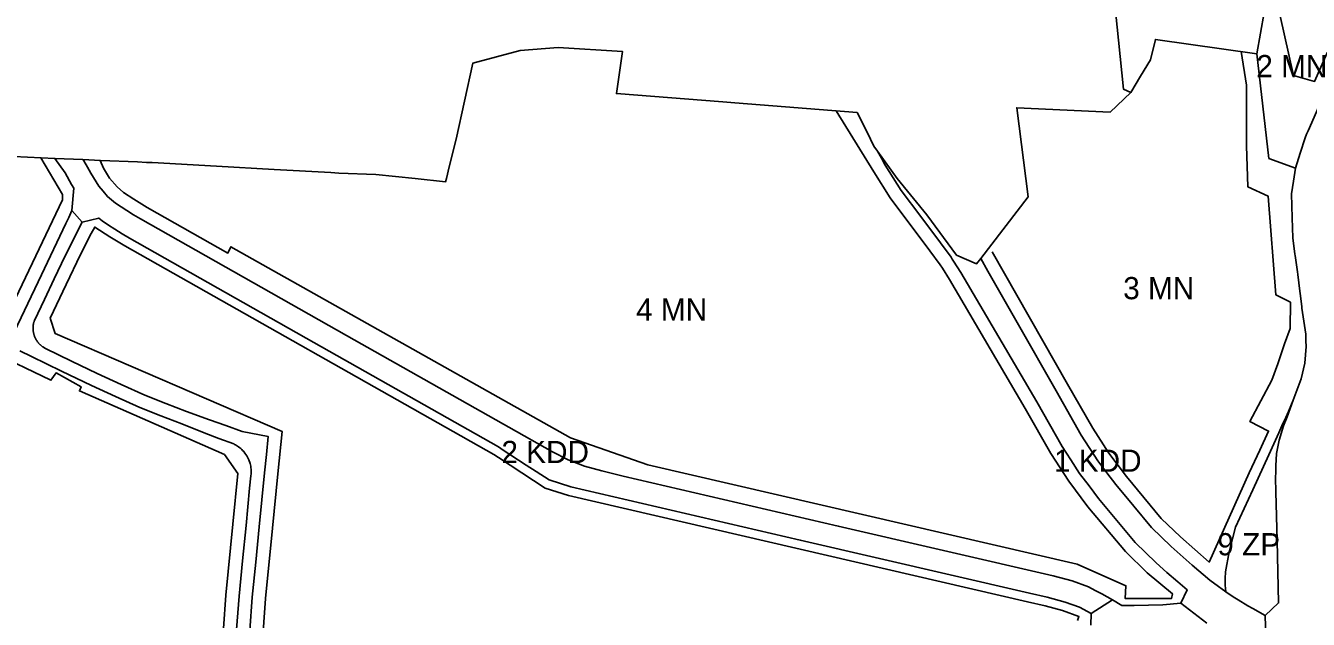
# Model space of a CAD drawing. Extents: x -294445 to -292055, y 21869 to 23693.
# Drawn here: x -294152 to -293575, y 22801 to 23069 of the extents above; entities that cross this region are included whole.
import ezdxf

# ---------------------------------------------------------------- set-up
doc = ezdxf.new("R2010")
doc.units = 0
for name, color, linetype in [('linie_rozgraniczajace', 7, 'Continuous'), ('linie_zabudowy_nieprzekraczalne', 7, 'Continuous'), ('oznaczenia_przeznaczen', 7, 'Continuous')]:
    doc.layers.add(name, color=color, linetype=linetype)

msp = doc.modelspace()

# ---------------------------------------------------------------- linework, layer by layer
at = {"layer": 'linie_rozgraniczajace'}
for points in [[(-293594.8, 23074.713), (-293598.18, 23056.18), (-293643.75, 23062.64), (-293646, 23053.44), (-293650.405, 23046.1), (-293654.81, 23038.76), (-293658.12, 23040.27), (-293663.22, 23090.34)], [(-293594.377, 22803.197), (-293588.38, 22808.908), (-293589.023, 22837.046), (-293589.523, 22858.895), (-293589.667, 22865.184), (-293589.623, 22867.888), (-293589.579, 22870.592), (-293589.304, 22876.246), (-293588.134, 22882.181), (-293586.073, 22888.643), (-293584.533, 22892.65), (-293583.08, 22896.428), (-293581.725, 22900.141), (-293578.212, 22909.773), (-293576.551, 22916.911), (-293575.931, 22924.43), (-293576.07, 22926.857), (-293576.139, 22929.92), (-293576.989, 22935.764), (-293577.839, 22941.607), (-293577.905, 22942.172), (-293578.488, 22947.138), (-293578.733, 22949.23), (-293579.627, 22956.854), (-293579.807, 22958.058), (-293580.261, 22961.104), (-293580.894, 22965.354), (-293580.971, 22965.973), (-293581.874, 22973.281), (-293582.075, 22977.797), (-293582.277, 22982.314), (-293582.433, 22987.716), (-293582.589, 22993.118), (-293581.675, 22998.875), (-293580.762, 23004.631), (-293578.598, 23011.442), (-293576.434, 23018.253), (-293575.727, 23019.979), (-293575.068, 23021.454), (-293563.422, 23048.255)], [(-294157.15, 23009.86), (-294138.732, 23009.066), (-294134.158, 23002.573), (-294131.211, 22997.34), (-294130.175, 22995.659), (-294131.07, 22985.54), (-294132.507, 22982.523), (-294133.797, 22979.815), (-294144.84, 22956.635), (-294158.61, 22927.73)], [(-293620.646, 22799.786), (-293632.243, 22808.79), (-293629.415, 22814.768), (-293633.738, 22818.381), (-293638.573, 22822.65), (-293643.408, 22826.92), (-293652.85, 22836.1), (-293661.114, 22846.024), (-293669.378, 22855.947), (-293673.604, 22861.583), (-293677.829, 22867.218), (-293681.733, 22873.257), (-293685.637, 22879.297), (-293691.388, 22889.378), (-293697.14, 22899.46), (-293714.205, 22928.55), (-293731.269, 22957.64), (-293732.897, 22960.234), (-293734.524, 22962.828), (-293735.093, 22963.688), (-293735.661, 22964.547), (-293740.366, 22971.031), (-293749.217, 22982.841), (-293758.069, 22994.65), (-293761.675, 23000.352), (-293765.28, 23006.054), (-293767.02, 23009.191), (-293768.761, 23012.328), (-293759.96, 23000), (-293746.54, 22983.64), (-293733.17, 22965.49), (-293724.23, 22961.52), (-293722.338, 22963.974), (-293719.124, 22958.324), (-293705.395, 22934.192), (-293688.451, 22904.41), (-293677.088, 22884.493), (-293669.62, 22872.939), (-293665.575, 22867.545), (-293661.531, 22862.15), (-293653.516, 22852.527), (-293645.502, 22842.903), (-293636.61, 22834.257), (-293627.186, 22825.936), (-293619.232, 22819.159), (-293615.314, 22816.339), (-293612.018, 22813.966), (-293608.745, 22811.61), (-293606.559, 22810.288), (-293602.186, 22807.646), (-293600, 22806.324), (-293594.377, 22803.197), (-293593.872, 22788.256)], [(-294158.61, 22927.73), (-294144.84, 22956.635), (-294133.797, 22979.815), (-294132.507, 22982.523), (-294131.07, 22985.54), (-294126.459, 22980.419), (-294132.54, 22968.508), (-294135.795, 22961.674), (-294139.05, 22954.84), (-294143.499, 22945.471), (-294147.949, 22936.102), (-294148.017, 22935.913), (-294148.081, 22935.721), (-294148.141, 22935.529), (-294148.198, 22935.336), (-294148.25, 22935.141), (-294148.299, 22934.945), (-294148.344, 22934.749), (-294148.385, 22934.551), (-294148.422, 22934.353), (-294148.455, 22934.154), (-294148.484, 22933.955), (-294148.509, 22933.755), (-294148.531, 22933.554), (-294148.548, 22933.353), (-294148.561, 22933.152), (-294148.57, 22932.951), (-294148.575, 22932.749), (-294148.577, 22932.548), (-294148.574, 22932.346), (-294148.567, 22932.145), (-294148.556, 22931.943), (-294148.542, 22931.742), (-294148.523, 22931.542), (-294148.5, 22931.341), (-294148.474, 22931.141), (-294148.443, 22930.942), (-294148.408, 22930.744), (-294148.37, 22930.546), (-294148.327, 22930.349), (-294148.281, 22930.152), (-294148.231, 22929.957), (-294148.177, 22929.763), (-294148.119, 22929.57), (-294148.057, 22929.378), (-294147.991, 22929.187), (-294147.922, 22928.998), (-294147.849, 22928.81), (-294147.772, 22928.624), (-294147.692, 22928.439), (-294147.608, 22928.256), (-294147.52, 22928.074), (-294147.429, 22927.894), (-294147.334, 22927.717), (-294147.235, 22927.541), (-294147.134, 22927.367), (-294147.028, 22927.195), (-294146.92, 22927.025), (-294146.808, 22926.857), (-294146.692, 22926.692), (-294146.574, 22926.529), (-294146.452, 22926.368), (-294146.327, 22926.21), (-294146.199, 22926.054), (-294146.068, 22925.901), (-294145.934, 22925.751), (-294145.797, 22925.603), (-294145.657, 22925.458), (-294145.514, 22925.316), (-294145.368, 22925.176), (-294145.22, 22925.04), (-294145.069, 22924.906), (-294144.915, 22924.776), (-294144.759, 22924.648), (-294144.6, 22924.524), (-294144.439, 22924.403), (-294144.275, 22924.285), (-294144.109, 22924.17), (-294143.941, 22924.059), (-294143.771, 22923.951), (-294143.707, 22923.912), (-294142.966, 22923.5), (-294131.334, 22917.829), (-294119.701, 22912.158), (-294108.982, 22907.305), (-294098.264, 22902.451), (-294088.881, 22898.77), (-294079.498, 22895.088), (-294069.14, 22891.36), (-294061.81, 22888.76), (-294054.48, 22886.16), (-294042.85, 22883.89), (-294043.645, 22875.72), (-294044.44, 22867.55), (-294045.63, 22855.355), (-294046.82, 22843.16), (-294048.39, 22827.29), (-294049.96, 22811.42), (-294051.011, 22796.447)], [(-294148.577, 22932.548), (-294148.575, 22932.749), (-294148.57, 22932.951), (-294148.561, 22933.152), (-294148.548, 22933.353), (-294148.531, 22933.554), (-294148.509, 22933.755), (-294148.484, 22933.955), (-294148.455, 22934.154), (-294148.422, 22934.353), (-294148.385, 22934.551), (-294148.344, 22934.749), (-294148.299, 22934.945), (-294148.25, 22935.141), (-294148.198, 22935.336), (-294148.141, 22935.529), (-294148.081, 22935.721), (-294148.017, 22935.913), (-294147.949, 22936.102), (-294143.499, 22945.471), (-294139.05, 22954.84), (-294135.795, 22961.674), (-294132.54, 22968.508), (-294126.459, 22980.419), (-294119.036, 22982.215), (-294117.521, 22980.923), (-294114.684, 22979.04), (-294111.847, 22977.158), (-294108.536, 22975.119), (-294105.226, 22973.08), (-294022.231, 22926.097), (-293939.236, 22879.115), (-293937.08, 22877.73), (-293926.755, 22870.99), (-293922.326, 22868.099), (-293916.467, 22864.266), (-293906.702, 22861.129), (-293803.525, 22837.225), (-293700.349, 22813.32), (-293692.398, 22811.487), (-293684.302, 22809.265), (-293677.89, 22806.933), (-293672.605, 22804.206), (-293672.799, 22798.844)], [(-294147.692, 22928.439), (-294147.772, 22928.624), (-294147.849, 22928.81), (-294147.922, 22928.998), (-294147.991, 22929.187), (-294148.057, 22929.378), (-294148.119, 22929.57), (-294148.177, 22929.763), (-294148.231, 22929.957), (-294148.281, 22930.152), (-294148.327, 22930.349), (-294148.37, 22930.546), (-294148.408, 22930.744), (-294148.443, 22930.942), (-294148.474, 22931.141), (-294148.5, 22931.341), (-294148.523, 22931.542), (-294148.542, 22931.742), (-294148.556, 22931.943), (-294148.567, 22932.145), (-294148.574, 22932.346), (-294148.577, 22932.548)], [(-294051.011, 22796.447), (-294049.96, 22811.42), (-294048.39, 22827.29), (-294046.82, 22843.16), (-294045.63, 22855.355), (-294044.44, 22867.55), (-294043.645, 22875.72), (-294042.85, 22883.89), (-294054.48, 22886.16), (-294061.81, 22888.76), (-294069.14, 22891.36), (-294079.498, 22895.088), (-294088.881, 22898.77), (-294098.264, 22902.451), (-294108.982, 22907.305), (-294119.701, 22912.158), (-294131.334, 22917.829), (-294142.966, 22923.5), (-294143.707, 22923.912), (-294143.771, 22923.951), (-294143.941, 22924.059), (-294144.109, 22924.17), (-294144.275, 22924.285), (-294144.439, 22924.403), (-294144.6, 22924.524), (-294144.759, 22924.648), (-294144.915, 22924.776), (-294145.069, 22924.906), (-294145.22, 22925.04), (-294145.368, 22925.176), (-294145.514, 22925.316), (-294145.657, 22925.458), (-294145.797, 22925.603), (-294145.934, 22925.751), (-294146.068, 22925.901), (-294146.199, 22926.054), (-294146.327, 22926.21), (-294146.452, 22926.368), (-294146.574, 22926.529), (-294146.692, 22926.692), (-294146.808, 22926.857), (-294146.92, 22927.025), (-294147.028, 22927.195), (-294147.134, 22927.367), (-294147.235, 22927.541), (-294147.334, 22927.717), (-294147.429, 22927.894), (-294147.52, 22928.074), (-294147.608, 22928.256), (-294147.692, 22928.439)], [(-294154.577, 22922.459), (-294149.34, 22919.92), (-294135.796, 22913.324), (-294122.252, 22906.727), (-294111.426, 22901.825), (-294100.599, 22896.922), (-294091.105, 22893.197), (-294081.611, 22889.472), (-294071.61, 22885.5), (-294064.97, 22882.989), (-294058.329, 22880.478), (-294057.979, 22880.268), (-294057.573, 22880.055), (-294057.092, 22879.779), (-294056.587, 22879.46), (-294056.171, 22879.174), (-294055.636, 22878.77), (-294055.183, 22878.394), (-294054.734, 22877.988), (-294054.307, 22877.565), (-294053.814, 22877.028), (-294053.288, 22876.384), (-294052.815, 22875.728), (-294052.434, 22875.134), (-294052.074, 22874.502), (-294051.756, 22873.867), (-294051.522, 22873.341), (-294051.313, 22872.812), (-294051.091, 22872.165), (-294050.935, 22871.631), (-294050.806, 22871.117), (-294050.678, 22870.493), (-294050.565, 22869.754), (-294050.497, 22869.087), (-294050.463, 22868.416), (-294050.459, 22867.875), (-294050.492, 22867.084), (-294050.603, 22866.172), (-294051.151, 22860.56), (-294051.971, 22852.154), (-294052.791, 22843.747), (-294054.365, 22827.836), (-294055.939, 22811.926), (-294056.993, 22796.91)], [(-294056.993, 22796.91), (-294055.939, 22811.926), (-294054.365, 22827.836), (-294052.791, 22843.747), (-294051.971, 22852.154), (-294051.151, 22860.56), (-294050.603, 22866.172), (-294050.492, 22867.084), (-294050.459, 22867.875), (-294050.463, 22868.416), (-294050.497, 22869.087), (-294050.565, 22869.754), (-294050.678, 22870.493), (-294050.806, 22871.117), (-294050.935, 22871.631), (-294051.091, 22872.165), (-294051.313, 22872.812), (-294051.522, 22873.341), (-294051.756, 22873.867), (-294052.074, 22874.502), (-294052.434, 22875.134), (-294052.815, 22875.728), (-294053.288, 22876.384), (-294053.814, 22877.028), (-294054.307, 22877.565), (-294054.734, 22877.988), (-294055.183, 22878.394), (-294055.636, 22878.77), (-294056.171, 22879.174), (-294056.587, 22879.46), (-294057.092, 22879.779), (-294057.573, 22880.055), (-294057.979, 22880.268), (-294058.329, 22880.478), (-294064.97, 22882.989), (-294071.61, 22885.5), (-294081.611, 22889.472), (-294091.105, 22893.197), (-294100.599, 22896.922), (-294111.426, 22901.825), (-294122.252, 22906.727), (-294135.796, 22913.324), (-294149.34, 22919.92), (-294154.577, 22922.459)], [(-293672.799, 22798.844), (-293672.605, 22804.206), (-293663.097, 22810.278), (-293658.78, 22807.8), (-293653.38, 22807.76), (-293646.929, 22807.926), (-293640.477, 22808.092), (-293632.243, 22808.79), (-293620.646, 22799.786)], [(-293574.744, 22625.222), (-293577.87, 22637.216), (-293579.304, 22644.235), (-293580.738, 22651.254), (-293582.053, 22659.409), (-293583.368, 22667.564), (-293584.1, 22672.161), (-293584.572, 22676.205), (-293585.045, 22680.249), (-293585.422, 22688.433), (-293585.799, 22696.617), (-293585.885, 22701.145), (-293585.97, 22705.674), (-293585.87, 22715.192), (-293585.77, 22724.711), (-293586.07, 22735.224), (-293586.369, 22745.737), (-293586.761, 22756.424), (-293587.153, 22767.111), (-293587.332, 22772.613), (-293587.511, 22778.115), (-293593.872, 22788.256), (-293594.377, 22803.197)]]:
    msp.add_lwpolyline(points, dxfattribs=at)
for points in [[(-293598.18, 23056.18), (-293594.8, 23074.713), (-293589.79, 23085.71), (-293551.776, 23075.056), (-293563.422, 23048.255), (-293575.068, 23021.454), (-293575.727, 23019.979), (-293576.434, 23018.253), (-293578.598, 23011.442), (-293580.762, 23004.631), (-293592.68, 23009.07)], [(-293722.338, 22963.974), (-293700.97, 22991.69), (-293706.09, 23031.87), (-293664.07, 23029.95), (-293654.81, 23038.76), (-293650.405, 23046.1), (-293646, 23053.44), (-293643.75, 23062.64), (-293598.18, 23056.18), (-293592.68, 23009.07), (-293580.762, 23004.631), (-293581.675, 22998.875), (-293582.589, 22993.118), (-293582.433, 22987.716), (-293582.277, 22982.314), (-293582.075, 22977.797), (-293581.874, 22973.281), (-293580.971, 22965.973), (-293580.894, 22965.354), (-293580.261, 22961.104), (-293579.807, 22958.058), (-293579.627, 22956.854), (-293578.733, 22949.23), (-293578.488, 22947.138), (-293577.905, 22942.172), (-293577.839, 22941.607), (-293576.989, 22935.764), (-293576.139, 22929.92), (-293576.07, 22926.857), (-293575.931, 22924.43), (-293576.551, 22916.911), (-293578.212, 22909.773), (-293581.725, 22900.141), (-293583.946, 22895.109), (-293585.157, 22892.364), (-293586.392, 22889.63), (-293588.262, 22885.537), (-293592.792, 22875.624), (-293600, 22859.85), (-293603.84, 22851.42), (-293607.68, 22842.99), (-293610.65, 22831.88), (-293612.28, 22822.97), (-293612.31, 22819.94), (-293612.34, 22816.91), (-293612.018, 22813.966), (-293615.314, 22816.339), (-293619.232, 22819.159), (-293627.186, 22825.936), (-293636.61, 22834.257), (-293645.502, 22842.903), (-293653.516, 22852.527), (-293661.531, 22862.15), (-293665.575, 22867.545), (-293669.62, 22872.939), (-293677.088, 22884.493), (-293688.451, 22904.41), (-293705.395, 22934.192), (-293719.124, 22958.324)], [(-294126.117, 23008.522), (-294118.18, 23008.18), (-294101.6, 23007.47), (-294097.5, 23007.29), (-294095.02, 23007.27), (-294066.09, 23005.62), (-294040.06, 23004.12), (-294014.7, 23002.66), (-294011.01, 23002.45), (-293994.39, 23001.87), (-293976.73, 23000), (-293963.03, 22998.55), (-293962.67, 23000), (-293961.4, 23005.29), (-293958.22, 23017.7), (-293950.78, 23051.9), (-293929.5, 23057.67), (-293912.35, 23058.96), (-293883.49, 23057.26), (-293886.21, 23038.22), (-293838.36, 23034.57), (-293832.98, 23034.12), (-293777.93, 23029.8), (-293773.46, 23020.81), (-293770.34, 23014.54), (-293768.761, 23012.328), (-293767.02, 23009.191), (-293765.28, 23006.054), (-293761.675, 23000.352), (-293758.069, 22994.65), (-293749.217, 22982.841), (-293740.366, 22971.031), (-293735.661, 22964.547), (-293735.093, 22963.688), (-293734.524, 22962.828), (-293732.897, 22960.234), (-293731.269, 22957.64), (-293714.205, 22928.55), (-293697.14, 22899.46), (-293691.388, 22889.378), (-293685.637, 22879.297), (-293681.733, 22873.257), (-293677.829, 22867.218), (-293673.604, 22861.583), (-293669.378, 22855.947), (-293661.114, 22846.024), (-293652.85, 22836.1), (-293643.408, 22826.92), (-293638.573, 22822.65), (-293633.738, 22818.381), (-293629.415, 22814.768), (-293632.243, 22808.79), (-293640.477, 22808.092), (-293646.929, 22807.926), (-293653.38, 22807.76), (-293658.78, 22807.8), (-293663.097, 22810.278), (-293667.82, 22812.99), (-293670.846, 22814.551), (-293673.872, 22816.113), (-293681.265, 22818.801), (-293689.751, 22821.13), (-293786.416, 22843.526), (-293883.08, 22865.921), (-293887.877, 22867.124), (-293892.674, 22868.327), (-293896.617, 22869.418), (-293900.561, 22870.51), (-293907.871, 22873.269), (-293914.956, 22876.861), (-294007.627, 22929.322), (-294100.299, 22981.782), (-294103.377, 22983.682), (-294106.455, 22985.581), (-294108.973, 22987.252), (-294111.49, 22988.922), (-294115.067, 22991.973), (-294117.039, 22994.289), (-294119.011, 22996.605), (-294122.595, 23002.419), (-294123.323, 23003.712), (-294124.144, 23005.17), (-294125.693, 23007.92)], [(-294138.732, 23009.066), (-294126.117, 23008.522), (-294125.693, 23007.92), (-294124.144, 23005.17), (-294123.323, 23003.712), (-294122.595, 23002.419), (-294119.011, 22996.605), (-294117.039, 22994.289), (-294115.067, 22991.973), (-294111.49, 22988.922), (-294108.973, 22987.252), (-294106.455, 22985.581), (-294103.377, 22983.682), (-294100.299, 22981.782), (-294007.627, 22929.322), (-293914.956, 22876.861), (-293907.871, 22873.269), (-293900.561, 22870.51), (-293896.617, 22869.418), (-293892.674, 22868.327), (-293887.877, 22867.124), (-293883.08, 22865.921), (-293786.416, 22843.526), (-293689.751, 22821.13), (-293681.265, 22818.801), (-293673.872, 22816.113), (-293670.846, 22814.551), (-293667.82, 22812.99), (-293663.097, 22810.278), (-293672.605, 22804.206), (-293677.89, 22806.933), (-293684.302, 22809.265), (-293692.398, 22811.487), (-293700.349, 22813.32), (-293803.525, 22837.225), (-293906.702, 22861.129), (-293916.467, 22864.266), (-293922.326, 22868.099), (-293926.755, 22870.99), (-293937.08, 22877.73), (-293939.236, 22879.115), (-294022.231, 22926.097), (-294105.226, 22973.08), (-294108.536, 22975.119), (-294111.847, 22977.158), (-294114.684, 22979.04), (-294117.521, 22980.923), (-294119.036, 22982.215), (-294126.459, 22980.419), (-294131.07, 22985.54), (-294130.175, 22995.659), (-294131.211, 22997.34), (-294134.158, 23002.573)], [(-293612.34, 22816.91), (-293612.31, 22819.94), (-293612.28, 22822.97), (-293610.65, 22831.88), (-293607.68, 22842.99), (-293603.84, 22851.42), (-293600, 22859.85), (-293592.792, 22875.624), (-293588.262, 22885.537), (-293586.392, 22889.63), (-293585.157, 22892.364), (-293583.946, 22895.109), (-293581.725, 22900.141), (-293583.08, 22896.428), (-293584.533, 22892.65), (-293586.073, 22888.643), (-293588.134, 22882.181), (-293589.304, 22876.246), (-293589.579, 22870.592), (-293589.623, 22867.888), (-293589.667, 22865.184), (-293589.523, 22858.895), (-293589.023, 22837.046), (-293588.38, 22808.908), (-293594.377, 22803.197), (-293600, 22806.324), (-293602.186, 22807.646), (-293606.559, 22810.288), (-293608.745, 22811.61), (-293612.018, 22813.966)]]:
    msp.add_lwpolyline(points, close=True, dxfattribs=at)
at = {"layer": 'linie_zabudowy_nieprzekraczalne'}
for points in [[(-293584.701, 23084.284), (-293587.714, 23073.836), (-293581.665, 23046.457), (-293572.15, 23043.741), (-293557.338, 23077.313), (-293552.486, 23090.161), (-293550.3, 23098.027), (-293547.513, 23111.254), (-293544.312, 23158.272), (-293553.385, 23244.347), (-293564.569, 23332.218), (-293570.426, 23331.686), (-293576.805, 23391.629), (-293581.064, 23437.909)], [(-293582.919, 22944.347), (-293589.634, 22947.638), (-293593.078, 22992.064), (-293602.252, 22996.302), (-293602.709, 23014.68), (-293602.755, 23037.217), (-293602.765, 23041.972), (-293605.213, 23057.177)], [(-294118.406, 23008.19), (-294116.933, 23004.669), (-294114.145, 23000.144), (-294110.809, 22996.227), (-294107.871, 22993.721), (-294103.22, 22990.635), (-294097.245, 22986.948), (-294060.964, 22966.41), (-294059.561, 22969.269), (-293906.834, 22883.185), (-293872.087, 22871.098), (-293678.874, 22826.313), (-293656.998, 22816.599), (-293657.302, 22810.832), (-293636.453, 22810.893), (-293636.123, 22813.052), (-293636.123, 22813.052), (-293647.488, 22822.517), (-293657.259, 22832.018), (-293674.087, 22852.225), (-293682.755, 22863.786), (-293690.766, 22876.179), (-293702.333, 22896.455), (-293736.399, 22954.527), (-293739.569, 22959.579), (-293740.594, 22961.129), (-293745.195, 22967.47), (-293763.013, 22991.242), (-293770.443, 23002.993), (-293787.304, 23030.536)], [(-294135.378, 22990.357), (-294135.378, 22992.778), (-294145.139, 23009.342)], [(-294164.065, 22930.23), (-294135.378, 22990.357)], [(-293678.724, 22801.02), (-293678.121, 22802.854), (-293685.517, 22805.45), (-293693.377, 22807.607), (-293701.25, 22809.423), (-293907.766, 22857.27), (-293918.165, 22860.606), (-293939.254, 22874.372), (-293941.304, 22875.689), (-294107.26, 22969.635), (-294114.002, 22973.787), (-294120.81, 22978.17), (-294122.369, 22975.236), (-294127.159, 22965.853), (-294133.633, 22952.26), (-294140.879, 22937.046)], [(-293717.123, 22966.941), (-293683.238, 22907.38), (-293671.959, 22887.61), (-293664.694, 22876.371), (-293656.822, 22865.872), (-293641.093, 22846.985), (-293632.53, 22838.659), (-293619.523, 22827.289), (-293601.635, 22867.436), (-293596.717, 22877.662), (-293592.854, 22886.299), (-293601.28, 22890.58), (-293591.38, 22909.15), (-293588.737, 22916.63), (-293585.725, 22925.561), (-293583.211, 22932.522), (-293582.919, 22944.347)], [(-294140.879, 22937.046), (-294138.65, 22930.285), (-294036.51, 22886.032), (-294038.468, 22866.968), (-294040.849, 22842.573), (-294043.981, 22810.914), (-294046.078, 22781.033)], [(-294064.031, 22782.337), (-294061.919, 22812.431), (-294058.762, 22844.333), (-294056.535, 22867.157), (-294062.486, 22875.79), (-294127.736, 22904.363), (-294127.736, 22904.363), (-294126.862, 22906.157), (-294138.25, 22912.482), (-294140.507, 22909.16), (-294167.636, 22922.124)]]:
    msp.add_lwpolyline(points, dxfattribs=at)

# ---------------------------------------------------------------- texts
at = {"layer": 'oznaczenia_przeznaczen'}
for s, p in [('2 MN', (-293598.369, 23045.609)), ('3 MN', (-293658.231, 22945.643)), ('4 MN', (-293877.319, 22935.979)), ('2 KDD', (-293937.906, 22871.861)), ('1 KDD', (-293689.355, 22867.939)), ('9 ZP', (-293615.891, 22830.327))]:
    msp.add_text(s, height=10, dxfattribs=at).set_placement(p)

doc.saveas('drawing.dxf')
